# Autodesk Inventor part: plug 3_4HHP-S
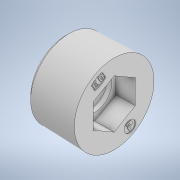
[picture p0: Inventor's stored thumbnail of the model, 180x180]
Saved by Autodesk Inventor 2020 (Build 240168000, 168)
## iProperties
Created: 2019-12
Part Number: plug 3_4HHP-S
Material: Generico
Description: STEP AP203
Document SubType Name: Modeling
Designer: carlo
Density: 1 g/cm^3
Appearance: Default
DataBaseUnit: MM
Title: p:/temp/worker_150/temp/exporttempdir_6516_1273_q2HQJ/format_0/Adapters Hexagon socket plug 3_4HHP-S.stp
Revision Number: NONE
Sending System: PARTsolutions
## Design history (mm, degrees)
feature "_Adapters Hexagon socket plug 3_4HHP-S"
node "Solido1"
